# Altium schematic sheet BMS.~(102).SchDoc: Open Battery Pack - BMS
size A3; Date: 26/03/2019; Author: Morgane Vallée - Samuel Lesueur; Revision: 1.0; SheetNumber: 1; SheetTotal: 5
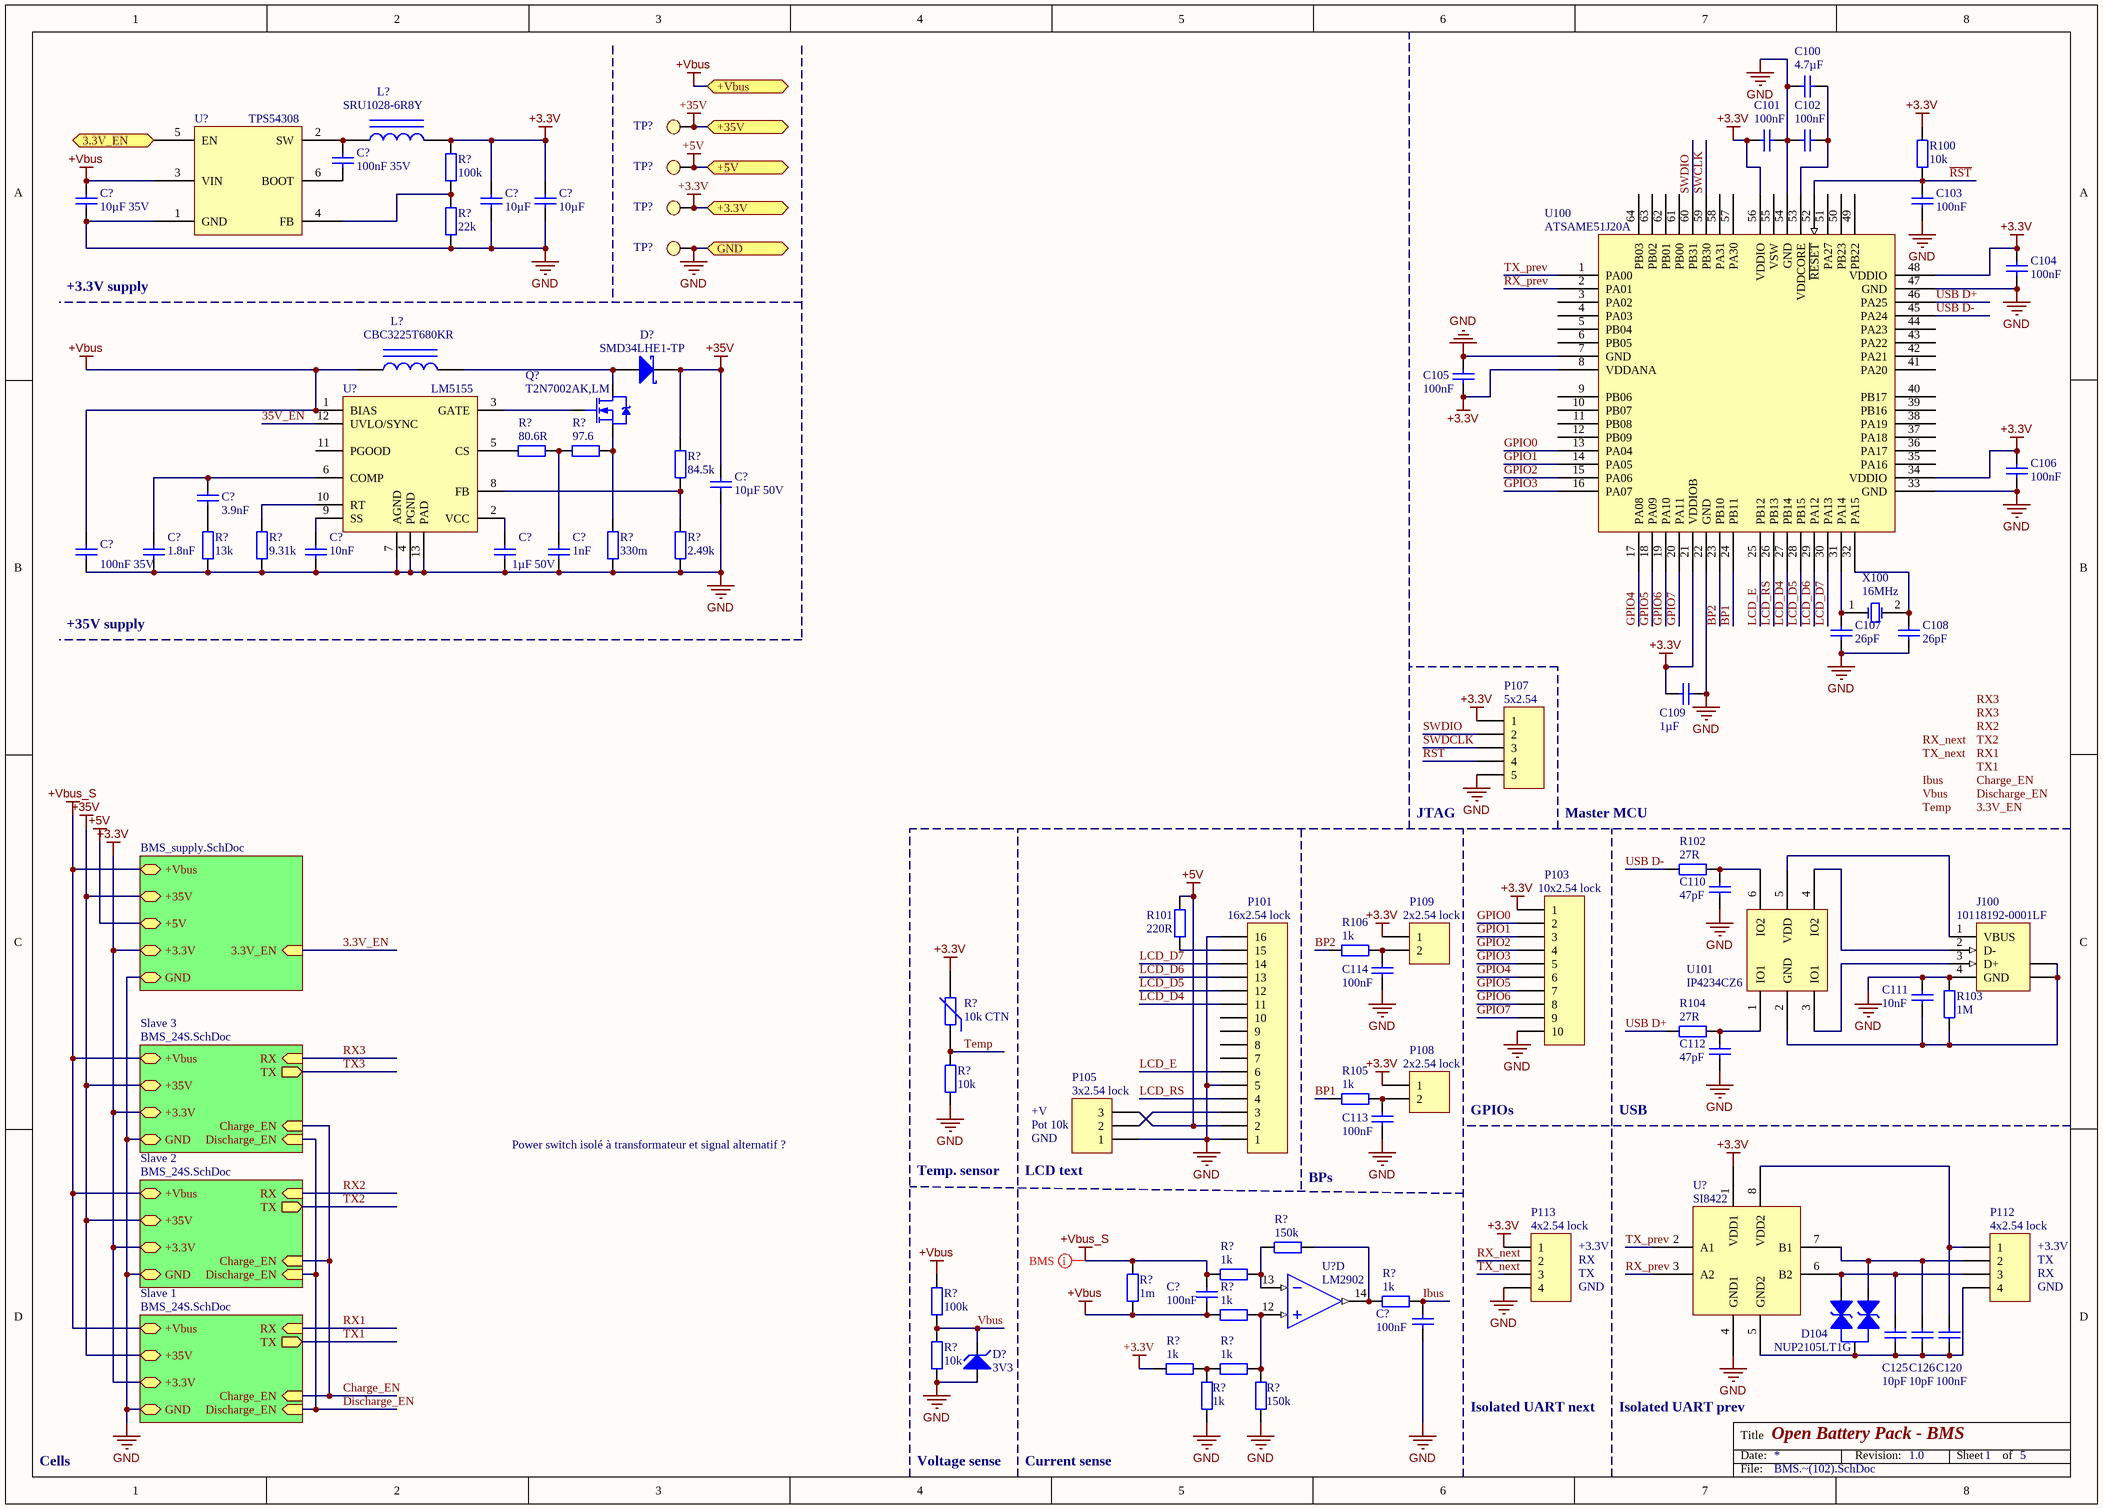
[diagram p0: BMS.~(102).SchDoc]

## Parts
(Parts that share a designator on the sheet are numbered #1, #2 ... from top to bottom, then left to right.)
C100  4.7µF  [C0603]
C101  100nF  [C0603]
C102  100nF  [C0603]
C103  100nF  [C0603]
C104  100nF  [C0603]
C105  100nF  [C0603]
C106  100nF  [C0603]
C107  26pF  [C0603]
C108  26pF  [C0603]
C109  1µF  [C0603]
C110  47pF  [C0603]
C111  10nF  [C0603]
C112  47pF  [C0603]
C113  100nF  [C0603]
C114  100nF  [C0603]
C120  100nF  [C0603]
C125  10pF  [C0603]
C126  10pF  [C0603]
C?#1  100nF 35V  [C0603]
C?#2  10µF 35V  [C0805]
C?#3  10µF  [C0603]
C?#4  10µF  [C0603]
C?#5  10µF 50V  [C0603]
C?#6  3.9nF  [C0603]
C?#7  100nF 35V  [C0603]
C?#8  1.8nF  [C0603]
C?#9  10nF  [C0603]
C?#10  1µF 50V  [C0805]
C?#11  1nF  [C0603]
C?#12  100nF  [C0603]
C?#13  100nF  [C0603]
D104  NUP2105LT1G  [DIODES SOT-23-3]
D?#1  SMD34LHE1-TP  [SOD-123H]
D?#2  3V3  [DIODE-0.7]
J100  10118192-0001LF  [FCI USB 10118193-0001LF]
L?#1  SRU1028-6R8Y  [FER 0805/2012]
L?#2  CBC3225T680KR  [SELF_SMD_8x8]
P101  16x2.54 lock  [HDR1X16]
P103  10x2.54 lock  [MOLEX KK 0022272101]
P105  3x2.54 lock  [MOLEX KK 0022272031]
P107  5x2.54  [HDR1X5]
P108  2x2.54 lock  [MOLEX KK 0022272021]
P109  2x2.54 lock  [MOLEX KK 0022272021]
P112  4x2.54 lock  [MOLEX SDA-70553-4PIN]
P113  4x2.54 lock  [MOLEX SDA-70553-4PIN]
Q?  T2N7002AK,LM  [TI SOT-23-3 DBZ]
R100  10k  [R0603]
R101  220R  [R0603]
R102  27R  [R0603]
R103  1M  [R0603]
R104  27R  [R0603]
R105  1k  [R0603]
R106  1k  [R0603]
R?#1  100k  [R0603]
R?#2  22k  [R0603]
R?#3  80.6R  [R0603]
R?#4  97.6  [R0603]
R?#5  84.5k  [R0603]
R?#6  13k  [R0603]
R?#7  9.31k  [R0603]
R?#8  330m  [R1206]
R?#9  2.49k  [R0603]
R?#10  10k CTN  [NTC 0402/1005]
R?#11  10k  [R0603]
R?#12  1k  [R0603]
R?#13  150k  [R0603]
R?#14  100k  [R0603]
R?#15  1m  [R1206]
R?#16  1k  [R0603]
R?#17  1k  [R0603]
R?#18  10k  [R0603]
R?#19  1k  [R0603]
R?#20  1k  [R0603]
R?#21  1k  [R0603]
R?#22  150k  [R0603]
TP?#1  Test Point  [Test Point]  (value not drawn)
TP?#2  Test Point  [Test Point]  (value not drawn)
TP?#3  Test Point  [Test Point]  (value not drawn)
TP?#4  Test Point  [Test Point]  (value not drawn)
U100  ATSAME51J20A  [TQFP-64N]
U101  IP4234CZ6  [VISHAY TSOP-6 MO-193C]
U?#1  TPS54308  [TI SOT-23-6 DDC]
U?#2  LM5155  [TI WSON-12]
U?#3  SI8422  [ANALOG SO-8 R-8]
U?#4  LM2902  [Atmel SO-14 14S1]  (part D of 5)
X100  16MHz  [ABRACON ABLS]

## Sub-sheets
Slave 1 = BMS_24S.SchDoc: +Vbus, +3.3V, GND, +35V, RX (in), TX (out), Charge_EN (in), Discharge_EN (in)
Slave 2 = BMS_24S.SchDoc: +Vbus, +3.3V, GND, +35V, RX (in), TX (out), Charge_EN (in), Discharge_EN (in)
Slave 3 = BMS_24S.SchDoc: +Vbus, +3.3V, GND, +35V, RX (in), TX (out), Charge_EN (in), Discharge_EN (in)
? = BMS_supply.SchDoc: +Vbus, +3.3V, GND, +35V, +5V, 3.3V_EN (in)

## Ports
3.3V_EN (in), +3.3V, +5V, +35V, +Vbus, GND

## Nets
+3.3V: C101.2 C104.2 C105.1 C106.2 C109.2 C?#3.1 C?#4.1 L?#1.2 P103.1 P107.1 P108.1 P109.1 P113.1 R100.2 R?#1.2 R?#10.2 R?#19.2 TP?#3.1 U100.8(VDDANA) U100.21(VDDIOB) U100.34(VDDIO) U100.48(VDDIO) U100.56(VDDIO) U?#3.1(VDD1) ; port +3.3V, sheet Slave 1/+3.3V, sheet /+3.3V, sheet Slave 2/+3.3V, sheet Slave 3/+3.3V
+5V: P101.2 P105.3 R101.2 TP?#2.1 ; port +5V, sheet /+5V
+35V: C?#5.1 D?#1.3(K) R?#5.2 TP?#1.1 ; port +35V, sheet Slave 1/+35V, sheet /+35V, sheet Slave 2/+35V, sheet Slave 3/+35V
+Vbus: C?#2.1 C?#7.1 C?#12.2 L?#2.1 R?#14.1 R?#15.1 R?#17.2 U?#1.3(VIN) U?#2.1(BIAS) ; port +Vbus
+Vbus_S: C?#12.1 R?#12.1 R?#15.2 ; sheet Slave 1/+Vbus, sheet /+Vbus, sheet Slave 2/+Vbus, sheet Slave 3/+Vbus
GND: C100.2 C101.1 C102.2 C103.1 C104.1 C105.2 C106.1 C107.1 C108.1 C109.1 C110.1 C111.2 C112.1 C113.1 C114.1 C?#2.2 C?#3.2 C?#4.2 C?#5.2 C?#7.2 C?#8.2 C?#9.2 C?#10.2 C?#11.2 C?#13.2 D?#2.1(A) J100.4(GND) P101.1 P101.5 P101.16 P103.10 P105.1 P107.5 P113.4 R103.1 R?#2.1 R?#6.1 R?#7.1 R?#8.1 R?#9.1 R?#11.2 R?#18.2 R?#20.2 R?#22.1 TP?#4.1 U100.7(GND) U100.22(GND) U100.33(GND) U100.47(GND) U100.54(GND) U?#1.1(GND) U?#2.4(PGND) U?#2.7(AGND) U?#2.13(PAD) U?#3.4(GND1) ; port GND, sheet Slave 1/GND, sheet /GND, sheet Slave 2/GND, sheet Slave 3/GND
3.3V_EN: U?#1.5(EN) ; port 3.3V_EN
35V_EN: U?#2.12(UVLO/SYNC)
BP1: R105.1 U100.24(PB11)
BP2: R106.1 U100.23(PB10)
Charge_EN: sheet Slave 1/Charge_EN, sheet Slave 2/Charge_EN, sheet Slave 3/Charge_EN
Discharge_EN: sheet Slave 1/Discharge_EN, sheet Slave 2/Discharge_EN, sheet Slave 3/Discharge_EN
GPIO0: P103.2 U100.13(PA04)
GPIO1: P103.3 U100.14(PA05)
GPIO2: P103.4 U100.15(PA06)
GPIO3: P103.5 U100.16(PA07)
GPIO4: P103.6 U100.17(PA08)
GPIO5: P103.7 U100.18(PA09)
GPIO6: P103.8 U100.19(PA10)
GPIO7: P103.9 U100.20(PA11)
Ibus: C?#13.1 R?#16.1
LCD_D4: P101.11 U100.27(PB14)
LCD_D5: P101.12 U100.28(PB15)
LCD_D6: P101.13 U100.29(PA12)
LCD_D7: P101.14 U100.30(PA13)
LCD_E: P101.6 U100.25(PB12)
LCD_RS: P101.4 U100.26(PB13)
~{RST}: C103.2 P107.4 R100.1 U100.52(~{RESET})
RX_next: P113.2
RX_prev: U100.2(PA01) U?#3.3(A2)
SWCLK: U100.59(PB30)
SWDCLK: P107.3
SWDIO: P107.2 U100.60(PB31)
Temp: R?#10.1 R?#11.1
TX_next: P113.3
TX_prev: U100.1(PA00) U?#3.2(A1)
USB D+: R104.1 U100.46(PA25)
USB D-: R102.1 U100.45(PA24)
Vbus: D?#2.2(K) R?#14.2 R?#18.1
NetC100_1: C100.1 C102.1 U100.53(VDDCORE)
NetC107_2: C107.2 U100.31(PA14) X100.1(OSC1)
NetC108_2: C108.2 U100.32(PA15) X100.2(OSC2)
NetC110_2: C110.2 R102.2 U101.6(IO2)
NetC111_1: C111.1 J100.5(SHLD) J100.6(SHLD) R103.2 U101.2(GND)
NetC112_2: C112.2 R104.2 U101.1(IO1)
NetC113_2: C113.2 P108.2 R105.2
NetC114_2: C114.2 P109.2 R106.2
NetC120_1: C120.1 C125.1 C126.1 D104.3 P112.4 U?#3.5(GND2)
NetC120_2: C120.2 P112.1 U?#3.8(VDD2)
NetC125_2: C125.2 D104.2 P112.3 U?#3.6(B2)
NetC126_2: C126.2 D104.1 P112.2 U?#3.7(B1)
NetC?#1_1: C?#1.1 L?#1.1 U?#1.2(SW)
NetC?#1_2: C?#1.2 U?#1.6(BOOT)
NetC?#6_1: C?#6.1 C?#8.1 U?#2.6(COMP)
NetC?#6_2: C?#6.2 R?#6.2
NetC?#9_1: C?#9.1 U?#2.9(SS)
NetC?#10_1: C?#10.1 U?#2.2(VCC)
NetC?#11_1: C?#11.1 R?#3.1 R?#4.2
NetD?#1_1: D?#1.1(A) L?#2.2 Q?.3(D)
NetJ100_1: J100.1(VBUS) U101.5(VDD)
NetJ100_2: J100.2(D-) U101.4(IO2)
NetJ100_3: J100.3(D+) U101.3(IO1)
NetP101_3: P101.3 P105.2
NetP101_15: P101.15 R101.1
NetQ?_1: Q?.1(G) U?#2.3(GATE)
NetQ?_2: Q?.2(S) R?#4.1 R?#8.2
NetR?#1_1: R?#1.1 R?#2.2 U?#1.4(FB)
NetR?#3_2: R?#3.2 U?#2.5(CS)
NetR?#5_1: R?#5.1 R?#9.2 U?#2.8(FB)
NetR?#7_2: R?#7.2 U?#2.10(RT)
NetR?#12_2: R?#12.2 R?#13.2 U?#4.13(IN-)
NetR?#13_1: R?#13.1 R?#16.2 U?#4.14(OUT)
NetR?#17_1: R?#17.1 R?#21.1 R?#22.2 U?#4.12(IN+)
NetR?#19_1: R?#19.1 R?#20.1 R?#21.2

Not connected (* = marked no-connect by the designer): P101 7 8 9 10; U100 3(PA02) 4(PA03) 5(PB04) 6(PB05) 9(PB06) 10(PB07) 11(PB08) 12(PB09) 35(PA16) 36(PA17) 37(PA18) 38(PA19) 39(PB16) 40(PB17) 41(PA20) 42(PA21) 43(PA22) 44(PA23) 49(PB22) 50(PB23) 51(PA27) 55(VSW) 57(PA30) 58(PA31) 61(PB00) 62(PB01) 63(PB02) 64(PB03); U?#2 11(PGOOD)

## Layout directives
net class BMS: +Vbus_S

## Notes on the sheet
- +3.3V supply
- +35V supply
- JTAG
- Master MCU
- (near P105) Pot 10k
- +V
- GPIOs
- USB
- Power switch isolé à transformateur et signal alternatif ?
- Temp. sensor
- (near P105) LCD text
- GND
- BPs
- (near P113) +3.3V
- (near P113) RX
- (near P112) +3.3V
- (near P112) TX
- (near P113) TX
- (near P113) GND
- (near P112) RX
- (near P112) GND
- Isolated UART next
- Isolated UART prev
- Cells
- Voltage sense
- Current sense
- Labels drawn without touching a wire or pin: 3.3V_EN, Charge_EN, Discharge_EN, Ibus, RX1, RX2, RX3, RX_next, Temp, TX1, TX2, TX_next, Vbus

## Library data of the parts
C100-C114 C120 C125 C126 C?#1-C?#13 = Cap: Capacitor
D104 = Dual Line TVS
D?#1 = Diode BAT17
D?#2 = Diode Zener
J100 = 1-353576-1: USB 1.1, Right Angle, SMT, A Type, Receptacle, 4 Position, White; pin to pad: 4>5 5>S 6>S
L?#1 L?#2 = Inductor Iron: Magnetic-Core Inductor
P101 = Header 16: Header, 16-Pin
P103 = Header 10: Header, 10-Pin
P105 = Header 3: Header, 3-Pin
P107 = Header 5: Header, 5-Pin
P108 P109 = Header 2: Header, 2-Pin
P112 P113 = Header 4H: Header, 4-Pin, Right Angle
Q? = MOSFET_N
R100-R106 R?#1-R?#9 R?#11-R?#22 = Res2: Resistor
R?#10 = Res Varistor: Varistor (Voltage-Sensitive Resistor)
U101 = IP4234CZ6: Single USB 2.0 ESD protection to IEC 61000-4-2 level 4
U?#1 = TPS54308: 4.5-V to 28-V Input, 3-A Output,  Synchronous 350-kHz FCCM Step-Down Converter in SOT23 Package
U?#2 = LM5155: 2.2-MHz Wide Input Nonsynchronous Boost, SEPIC, Flyback Controller
U?#3 = SI8422: Low-Power, Dual-Channel Digital Isolators
U?#4 = LM2902: Low-power quad operational amplifiers
X100 = XTAL: Crystal Oscillator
